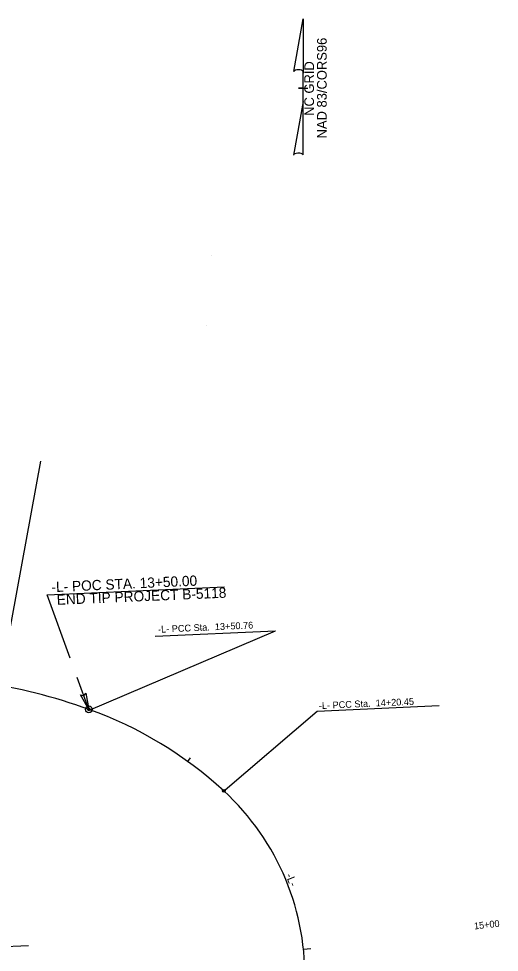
# Model space of a CAD drawing. Extents: x 1191189 to 1191812, y 892693 to 893370.
# Drawn here: x 1191601 to 1191812.1, y 892960.4 to 893370.4 of the extents above; entities that cross this region are included whole.
import ezdxf

# ---------------------------------------------------------------- set-up
doc = ezdxf.new("R2010")
doc.units = 0
for name, color, linetype in [('Prop Horizontal Alignment', 7, 'Continuous'), ('Prop Horizontal Alignment Station Label', 7, 'Continuous'), ('Prop Horizontal Alignment Tick Label', 7, 'Continuous'), ('Prop Horizontal Alignment Tick Large', 7, 'Continuous'), ('Prop Horizontal Alignment Tick Small', 7, 'Continuous'), ('Prop Leader Line Medium', 7, 'Continuous'), ('Prop North Arrow NAD83 for Plan Sheets CELL', 7, 'Continuous'), ('Prop Terminator CELL', 7, 'Continuous'), ('Scratch_Level_1', 7, 'Continuous')]:
    doc.layers.add(name, color=color, linetype=linetype)

msp = doc.modelspace()

# ---------------------------------------------------------------- linework, layer by layer
at = {"layer": 'Prop Horizontal Alignment'}
for centre, radius, start, end in [((1191547.39, 892831.78), 250, 70.2703, 92.6195), ((1191572.71, 892902.38), 175, 47.4533, 70.2703), ((1191616.66, 892950.27), 110, 357.6307, 47.4533)]:
    msp.add_arc(centre, radius, start, end, dxfattribs=at)
at = {"layer": 'Prop Horizontal Alignment Station Label'}
for p, q in [((1191631.59, 893066.54), (1191713.84, 893101.65)), ((1191660.86, 893099.23), (1191713.84, 893101.65)), ((1191732.06, 893066.29), (1191785.71, 893068.74)), ((1191690.64, 893030.87), (1191732.06, 893066.29)), ((1191541.5, 892960.51), (1191605.25, 892963.43))]:
    msp.add_line(p, q, dxfattribs=at)
for centre, radius in [((1191631.79, 893067.11), 1.5), ((1191631.79, 893067.11), 0.6), ((1191691.05, 893031.31), 0.6)]:
    msp.add_circle(centre, radius, dxfattribs=at)
at = {"layer": 'Prop Horizontal Alignment Tick Large'}
msp.add_line((1191726.06, 892961.8), (1191729.24, 892962.13), dxfattribs=at)
at = {"layer": 'Prop Horizontal Alignment Tick Small'}
msp.add_line((1191675.21, 893044.22), (1191676.38, 893045.84), dxfattribs=at)
at = {"layer": 'Prop Leader Line Medium'}
for p, q in [((1191613.48, 893117.33), (1191691.38, 893120.89)), ((1191623.59, 893089.58), (1191613.48, 893117.33)), ((1191631.79, 893067.11), (1191626.66, 893081.16))]:
    msp.add_line(p, q, dxfattribs=at)
at = {"layer": 'Prop North Arrow NAD83 for Plan Sheets CELL'}
for p, q in [((1191721.78, 893347.24), (1191725.88, 893370.41)), ((1191725.91, 893370.41), (1191725.91, 893346.51)), ((1191725.91, 893334.11), (1191725.91, 893347.21)), ((1191725.91, 893346.51), (1191725.91, 893347.19)), ((1191725.68, 893339.91), (1191723.91, 893339.91)), ((1191723.93, 893339.91), (1191727.93, 893339.91)), ((1191725.91, 893334.11), (1191721.73, 893310.49)), ((1191725.93, 893310.59), (1191725.91, 893334.11)), ((1191685.65, 893266.24), (1191685.63, 893266.24)), ((1191685.65, 893266.24), (1191685.63, 893266.24)), ((1191683.65, 893235.74), (1191683.63, 893235.74))]:
    msp.add_line(p, q, dxfattribs=at)
for centre, start_param, end_param in [((1191723.85, 893346.99), 0.216388, 2.908219), ((1191723.85, 893310.4), 0.201328, 3.141593)]:
    msp.add_ellipse(centre, major_axis=(2.11, -0.02), ratio=0.461098, start_param=start_param, end_param=end_param, dxfattribs=at)
at = {"layer": 'Prop Terminator CELL'}
msp.add_lwpolyline([(1191630.47, 893074.29), (1191631.79, 893067.11), (1191628.09, 893073.46), (1191629.61, 893073.04)], close=True, dxfattribs=at)
at = {"layer": 'Scratch_Level_1'}
msp.add_line((1191610.51, 893176.05), (1191574.44, 892979.32), dxfattribs=at)

# ---------------------------------------------------------------- texts
at = {"layer": 'Prop Horizontal Alignment Station Label'}
for s, p in [('-L- PCC Sta.  13+50.76', (1191662.27, 893100.72)), ('-L- PCC Sta.  14+20.45', (1191732.91, 893067.21))]:
    msp.add_text(s, height=3, rotation=2.6195, dxfattribs=at).set_placement(p)
at = {"layer": 'Prop Horizontal Alignment Tick Label'}
msp.add_text('15+00', height=3, rotation=6.016, dxfattribs=at).set_placement((1191801.13, 892970.45))
at = {"layer": 'Prop Leader Line Medium'}
for s, height, rotation, p in [('-L- POC STA. 13+50.00', 4.5, 2.5888, (1191615.46, 893118.55)), ('END TIP PROJECT B-5118', 4.5, 2.4356, (1191617.78, 893112.99)), ('-L- ', 3.5, 291.683, (1191718.16, 892994.26))]:
    msp.add_text(s, height=height, rotation=rotation, dxfattribs=at).set_placement(p)
at = {"layer": 'Prop North Arrow NAD83 for Plan Sheets CELL'}
for s, p in [('NAD 83/CORS96', (1191736.27, 893317.83)), ('NC GRID', (1191730.7, 893327.73))]:
    msp.add_text(s, height=4.25, rotation=90, dxfattribs=at).set_placement(p)

doc.saveas('drawing.dxf')
